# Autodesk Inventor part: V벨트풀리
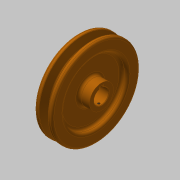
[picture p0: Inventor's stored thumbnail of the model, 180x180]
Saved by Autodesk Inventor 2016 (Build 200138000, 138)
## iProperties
Created: 2015-11
Part Number: V벨트풀리
Material: 강철, 탄소
Document SubType Name: Modeling
Designer: mduedu
Density: 1 g/cm^3
Appearance: 주황색
Author: mduedu
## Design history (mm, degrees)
sketch "스케치1"
  geometry: L1 (-9.5, 0)-(9.5, 0); L2 (0, 0)-(0, 47.7); L3 (-4.877, 47.7)-(-9.5, 47.7); L4 (-9.5, 47.7)-(-9.5, 0); L5 (0, 38.7)-(-1.953, 38.7); L6 (-1.953, 38.7)-(-4.877, 47.7); L7 (4.877, 47.7)-(9.5, 47.7); L8 (9.5, 47.7)-(9.5, 0); L9 (0, 38.7)-(1.953, 38.7); L10 (1.953, 38.7)-(4.877, 47.7); L11 (-9.5, 45)-(9.5, 45); 3 further points
  constraints: 22 end point, 7 point on line, 4 perpendicular, 3 symmetric about line, 1 coincident, 1 horizontal, 1 horizontal alignment, 1 midpoint, 1 vertical
  dimensions: "d0" = 19 distance of L1.start L1.end; "d2" = 95.4 diameter of L2.end L1 (derived); "d3" = 36 deg angle of L10 L6; "d4" = 6.3 distance between parallel lines of L11 L9; "d5" = 2.7 distance between parallel lines of L7 L11; "d6" = 8 distance of point (4, 45) point (-4, 45); "d7" = 90 diameter of L11 L1
revolve "회전1" sketch "스케치1" stored, may be unused: angle "d8" = 90 deg
sketch "스케치2"
  geometry: C1 r 34 at (0, 0); C2 r 13 at (0, 0); 1 further point
  constraints: 2 centre point, 2 coincident
  dimensions: "d9" = 68 diameter of C1; "d10" = 26 diameter of C2
extrude "돌출1" cut sketch "스케치2" distance "d11" = 6; taper "d12" = 0 deg
extrude "돌출3" join sketch "스케치2" distance "d37" = 6; taper "d38" = 0 deg
fillet "모깎기1" dims "d13" = 3
fillet "모깎기2" dims "d14" = 3
fillet "모깎기3" dims "d15" = 1, "d16" = 0.5, "d17" = 2
hole "구멍1" diameter "d20" = 16; stored, may be unused: countersink angle "d24" = 90 deg, drill point angle "d26" = 118 deg; dims "d21" = 6, "d22" = 4, "d23" = 2, "d25" = 8, "d53" = 10, "d54" = 10
sketch "스케치3"
  geometry: L1 (-2.5, 0)-(2.5, 0); L2 (2.5, 0)-(2.5, 10.3); L3 (2.5, 10.3)-(-2.5, 10.3); L4 (-2.5, 10.3)-(-2.5, 0); 2 further points
  constraints: 8 end point, 2 parallel, 1 coincident, 1 horizontal, 1 midpoint, 1 perpendicular
  dimensions: "d27" = 5 distance of L2.end L3.end; "d29" = 10.3 distance of L3.end L1.start
extrude "돌출2" cut sketch "스케치3" stored distance "d30" = 6; taper "d31" = 0 deg
node "작업 평면1"
sketch "스케치4"
  geometry: L1 (19, -37)-(19, 37) reference; 2 further points
  constraints: 1 horizontal alignment
  dimensions: "d52" = 22 distance from line of L1 point (-3, 0)
hole "구멍2" sketch "스케치4" at (-3, 0) diameter "d42" = 2.459; stored, may be unused: countersink angle "d46" = 90 deg, drill point angle "d48" = 118 deg; dims "d43" = 6, "d44" = 4, "d45" = 2, "d47" = 8
chamfer "모따기3" distance "d58" = 0.5; stored, may be unused: second distance "d59" = 2, angle "d60" = 45 deg
node "솔리드1"
mirror "대칭1"
